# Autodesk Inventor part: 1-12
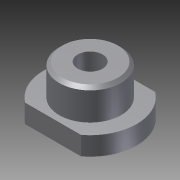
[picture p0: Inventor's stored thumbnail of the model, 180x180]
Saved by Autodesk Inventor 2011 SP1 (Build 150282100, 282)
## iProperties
Created: 2014-02
Part Number: 1-12
Document SubType Name: Modeling
Designer: Administrator
Density: 1 g/cm^3
Author: Administrator
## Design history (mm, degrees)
sketch "草图1"
  geometry: L1 (-9, 12)-(9, 12); L2 (-9, -12)-(9, -12); A1 r 15 centre (0, 0) between (9, -12) and (9, 12); A2 r 15 centre (0, 0) between (-9, 12) and (-9, -12); 1 further point
  constraints: 4 end point, 4 point on circle, 2 centre point, 1 coincident, 1 parallel
extrude "拉伸1" new body sketch "草图1" distance "d3" = 6; taper "d4" = 0 deg
sketch "草图2"
  geometry: C1 r 10 at (0, 0); A1 r 15 centre (0, 0) between (-9, 12) and (-9, -12) reference
  constraints: 1 centre point, 1 coincident
extrude "拉伸2" join sketch "草图2" distance "d5" = 10; taper "d6" = 0 deg
chamfer "倒角1" distance "d7" = 1; stored, may be unused: second distance "d8" = 2, angle "d9" = 45 deg
sketch "草图3"
  geometry: C1 r 9 at (0, 0) reference; C2 r 4 at (0, 0)
  constraints: 1 centre point, 1 coincident
  dimensions: "d10" = 8 diameter of C2
extrude "拉伸3" cut sketch "草图3" stored distance "d11" = 10; taper "d12" = 0 deg
chamfer "倒角2" distance "d13" = 1; stored, may be unused: second distance "d14" = 2, angle "d15" = 45 deg
node "实体1"
